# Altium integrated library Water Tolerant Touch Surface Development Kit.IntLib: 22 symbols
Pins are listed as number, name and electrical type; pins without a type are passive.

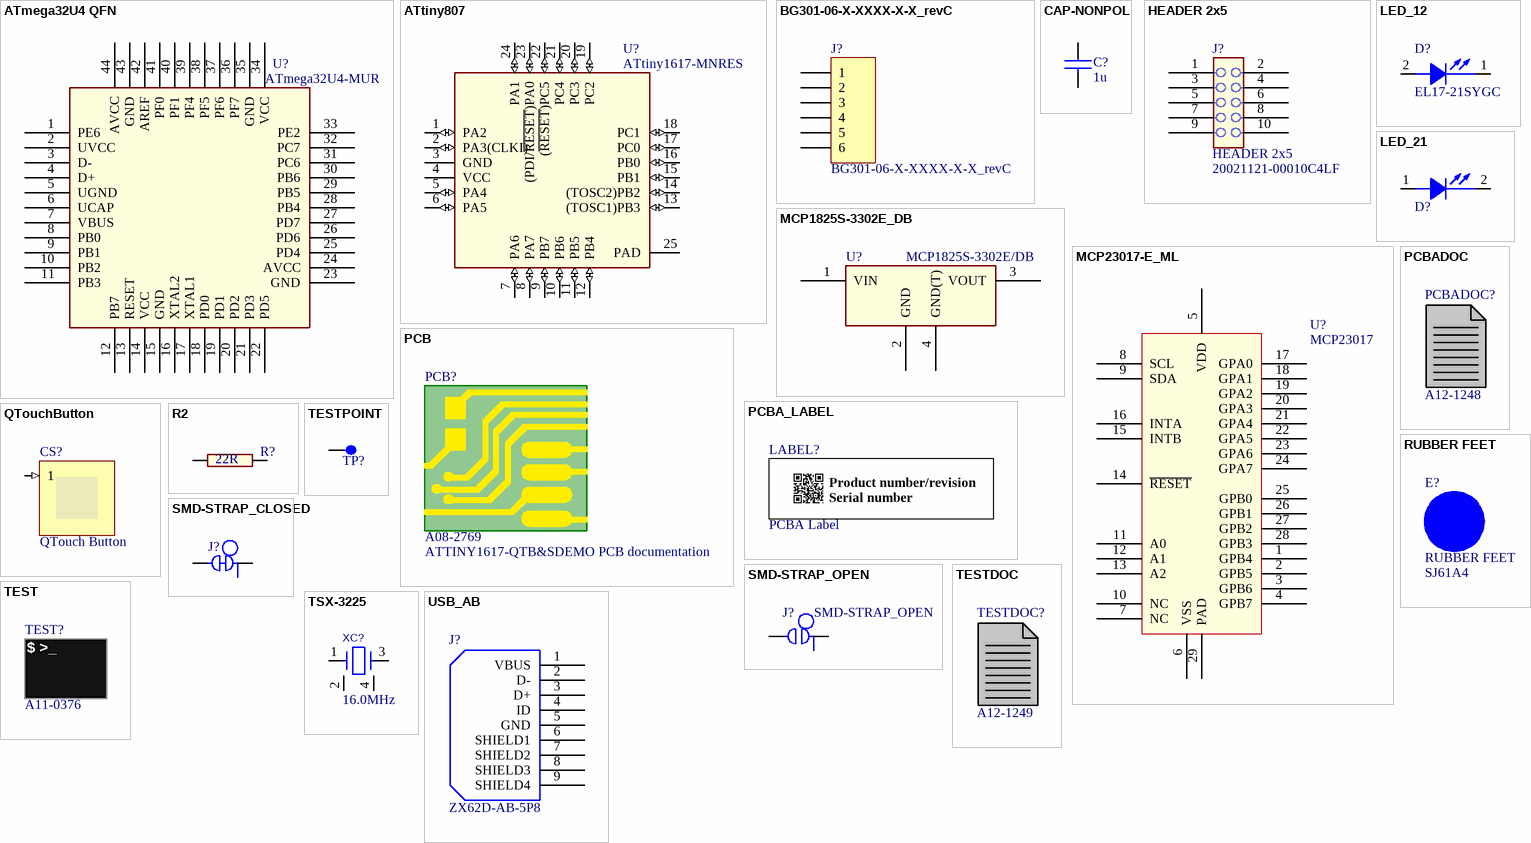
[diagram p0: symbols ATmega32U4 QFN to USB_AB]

## ATmega32U4 QFN
designator U?  value ATmega32U4-MUR
ATmega32U4 QFN package; PartGroup: Integrated Circuits,MCU, MPU, DSP,AVR MCU; Manufacturer: ATMEL; AN: A06-0305; ComponentStatus: 'Active (verified)'
footprint AP6-00375
pins: 1 PE6, 2 UVCC (power), 3 D-, 4 D+, 5 UGND (power), 6 UCAP (power), 7 VBUS (power), 8 PB0, 9 PB1, 10 PB2, 11 PB3, 12 PB7, 13 RESET, 14 VCC, 15 GND, 16 XTAL2, 17 XTAL1, 18 PD0, 19 PD1, 20 PD2, 21 PD3, 22 PD5, 23 GND (power), 24 AVCC (power), 25 PD4, 26 PD6, 27 PD7, 28 PB4, 29 PB5, 30 PB6, 31 PC6, 32 PC7, 33 PE2, 34 VCC (power), 35 GND (power), 36 PF7, 37 PF6, 38 PF5, 39 PF4, 40 PF1, 41 PF0, 42 AREF (power), 43 GND (power), 44 AVCC (power), 45 GND hidden to GND "PAD"

## ATtiny807
designator U?  value ATtiny1617-MNRES  (hidden comment: ATtiny807)
Atmel 8-bit RISC MCU, QFN; PartGroup: Integrated Circuits,MCU, MPU, DSP,AVR MCU; AN: A06-1500; TemperatureRange: -40Â°C +125Â°C; ComponentStatus: 'Active (verified)'
footprint AP6-00459
pins: 1 PA2 (io), 2 PA3(CLKI) (io), 3 GND (power), 4 VCC (power), 5 PA4 (io), 6 PA5 (io), 7 PA6 (io), 8 PA7 (io), 9 PB7 (io), 10 PB6 (io), 11 PB5 (io), 12 PB4 (io), 13 (TOSC1)PB3 (io), 14 (TOSC2)PB2 (io), 15 PB1 (io), 16 PB0 (io), 17 PC0 (io), 18 PC1 (io), 19 PC2 (io), 20 PC3 (io), 21 PC4 (io), 22 (~{RESET})PC5 (io), 23 (PDI/~{RESET})PA0 (io), 24 PA1 (io), 25 PAD (power)

## BG301-06-X-XXXX-X-X_revC
designator J?
2.54mm Pitch Pin Header,Single Row, Surface Mount, Horizontal, Natural LCP
footprint BG301-06-X-XXXX-X-X_revC (2.54mm Pitch Pin Header,Single Row, Surface Mount, Horizontal, Natural LCP)
pins: 1, 2, 3, 4, 5, 6

## CAP-NONPOL
designator C?  value 1u
Ceramic capacitor, SMD 0402, X5R, 6.3V, +/-10% (de26942); PartGroup: Capacitors,Ceramic,SMD 0402; Manufacturer: Kemet; MPN: C0402C105K9PAC; AN: A01-0286; TemperatureRange: -55 to 85 deg C; ComponentStatus: 'Active (verified)'
footprint AP1-00001
pins: 1, 2

## HEADER 2x5
designator J?  value 20021121-00010C4LF
2x5 pin header, 1.27mm pitch, SMD; PartGroup: Mechanical devices,Connectors,Pin headers; Manufacturer: HARWIN; MPN: M50-3600542; AN: A08-0022; ComponentStatus: 'Active (verified)'
footprint AP8-00109
pins: 1, 2, 3, 4, 5, 6, 7, 8, 9, 10
1 alternate drawing of the same symbol

## LED_12
designator D?  value EL17-21SYGC
LED, Green, Wave length=575nm, SMD 0805, ±70°; PartGroup: Opto,LEDs,SMD; Manufacturer: Everlight; AN: A10-0018; TemperatureRange: -40 - +85 deg C; ComponentStatus: 'Active (verified)'
footprint AP4-00013
pins: 1 CATHODE, 2 ANODE

## LED_21
designator D?  (value not drawn)
LED, SMD, RED, 3.2x1.2mm, reverse mount; AN: A10-0204; Value: LTST-C250KRKT
footprint AP4-00115
pins: 1 ANODE, 2 CATHODE

## MCP1825S-3302E_DB
designator U?  value MCP1825S-3302E/DB  (hidden comment: MCP1825S-3302E_DB)
LDO regulator, 3.3V fixed, 500mA, SOT-223; AN: A06-1533
pins: 1 VIN (power), 2 GND (power), 3 VOUT (power), 4 GND(T) (power)

## MCP23017-E_ML
designator U?  value MCP23017  (hidden comment: MCP23017-E_ML)
16-Bit I/O Expander with I2C interface, 28-Lead QFN; PartGroup: Integrated Circuits,General linear; Manufacturer: Microchip Technology Inc; MPN: MCP23017-E/ML; AN: A06-1534; TemperatureRange: -40Â°C to +125Â°C; ComponentStatus: 'Active (verified)'
footprint AP6-00497
pins: 1 GPB4, 2 GPB5, 3 GPB6, 4 GPB7, 5 VDD, 6 VSS, 7 NC, 8 SCL, 9 SDA, 10 NC, 11 A0, 12 A1, 13 A2, 14 ~{RESET}, 15 INTB, 16 INTA, 17 GPA0, 18 GPA1, 19 GPA2, 20 GPA3, 21 GPA4, 22 GPA5, 23 GPA6, 24 GPA7, 25 GPB0, 26 GPB1, 27 GPB2, 28 GPB3, 29 PAD

## PCB
designator PCB?  value ATTINY1617-QTB&SDEMO PCB documentation  AN: A08-2769  (hidden comment: PCB)  (mechanical)
ATTINY1617-QTB&SDEMO PCB documentation

## PCBA_LABEL
designator LABEL?  value PCBA Label  (hidden comment: PCBA_LABEL)
PCBA identification label PP Top White Gloss; PartGroup: Mechanical devices,Packaging materials,Printed Labels; Manufacturer: ACT Logimark AS; MPN: 505462; AN: A09-0611; ComponentStatus: 'Active (verified)'
footprint AP8-00317

## PCBADOC
designator PCBADOC?  AN: A12-1248  (hidden comment: PCBADOC)  (mechanical)
ATTINY1617-QTB&SDEMO PCBA documentation

## QTouchButton
designator CS?, comment QTouch Button  (graphical)
ConfiguratorName: ATMEL_TOUCH; ConfigurationParameters: {}__sensorid[1]{}width[8]{}height[8]{}
pins: 1 (in)

## R2
designator R?  value 22R
Thick film resistor, SMD 0402, 1/16W, 1% (de23607); PartGroup: Resistors,SMD,0402 1%; Manufacturer: Samsung; MPN: RC100SF22R0CS; AN: A02-0172; TemperatureRange: -55 - +125 deg C; ComponentStatus: 'Active (verified)'
footprint AP2-00000
pins: 1, 2

## RUBBER FEET
designator E?  value SJ61A4
7.9mm adhesive feet diam 9.5mm; AN: A08-2771
footprint AP8-01069
pins: 1 FIDUCIAL

## SMD-STRAP_CLOSED
designator J?  (net tie, no BOM)
Default closed SMD strap, 0603 size; PartGroup: Mechanical devices,PCB implemented components; AN: A09-0783; Value: SMD-STRAP_0603_CLOSED; ComponentStatus: 'Active (verified)'
footprint AP9-00044
pins: 1, 2

## SMD-STRAP_OPEN
designator J?  value SMD-STRAP_OPEN  (no BOM)
Default open SMD strap; PartGroup: Mechanical devices,PCB implemented components; AN: A09-0483; ComponentStatus: 'Active (verified)'
footprint AP9-00034
pins: 1, 2

## TEST
designator TEST?  AN: A11-0376  (hidden comment: TEST)  (mechanical)
ATTINY1617-QTB&SDEMO Test Software

## TESTDOC
designator TESTDOC?  AN: A12-1249  (hidden comment: TESTDOC)  (mechanical)
ATTINY1617-QTB&SDEMO Test Instructions

## TESTPOINT
designator TP?  (no BOM)
Single SMD testpad; PartGroup: Mechanical devices,Connectors,Test points; AN: A08-0004; ComponentStatus: 'Active (verified)'
footprint AP8-00010
pins: 1

## TSX-3225
designator XC?  value 16.0MHz
16MHz uXtal, 3.2 x 2.5 mm SMD, CL=9pF, 15PPM, ESR=80ohm(Max.; PartGroup: Frequency devices,Crystals,SMD; Manufacturer: Epson Toyocom; MPN: TSX-3225 16.0000MF09Z-AC3; AN: A07-0078; TemperatureRange: -40Â°C to +85Â°C; ComponentStatus: 'Active (verified)'
footprint AP7-00061 (TSX-3225)
pins: 1 IN, 2 GND, 3 OUT, 4 GND

## USB_AB
designator J?, comment value ZX62D-AB-5P8  (hidden comment: 2,000 pieces per reel)
Micro USB AB Connector, Standard SMT + DIP; PartGroup: Mechanical devices,Connectors,USB; Manufacturer: HIROSE; MPN: ZX62D-AB-5P8(30); AN: A08-2112; ComponentStatus: 'Active (verified)'
footprint AP8-00852
pins: 1 VBUS, 2 D-, 3 D+, 4 ID, 5 GND, 6 SHIELD1, 7 SHIELD2, 8 SHIELD3, 9 SHIELD4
